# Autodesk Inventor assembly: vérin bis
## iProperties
Shininess: 41.0
Length Units: 11269
Angle Units: 11279
Time Units: 11290
Mass Units: 11283
Length Display Precision: 3
Angle Display Precision: 2
Created: 2002-06
Part Number: vérin bis
Document SubType Name: Assemblage
Designer: REVEST Pierre
Density: 0.0
Volumn: 0.0
Area: 0.0
PropertySet Name: Model Information
Control State: 0
Master: False
Checked Out: False
Author: REVEST Pierre
